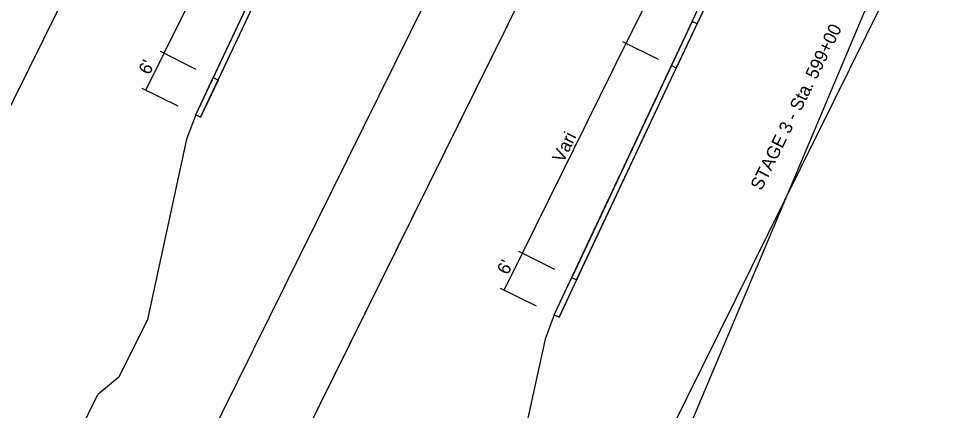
# Model space of a CAD drawing. Extents: x 14104283 to 14120882, y 8635219 to 8671666.
# Drawn here: x 14118051 to 14118626, y 8668145 to 8668387 of the extents above; entities that cross this region are included whole.
import ezdxf

# ---------------------------------------------------------------- set-up
doc = ezdxf.new("R2010")
doc.units = 0
for name, color, linetype in [('Default', 7, 'Continuous'), ('dsnNonPlotable', 7, 'Continuous'), ('dsnStgShadingPrevPav', 7, 'Continuous'), ('dsnTextFinalPlan', 7, 'Continuous'), ('dsnTextOverlapEven', 7, 'Continuous'), ('TC_SubstrataExistingPavement', 7, 'Continuous'), ('Terrain', 7, 'Continuous')]:
    doc.layers.add(name, color=color, linetype=linetype)

msp = doc.modelspace()

# ---------------------------------------------------------------- linework, layer by layer
at = {"layer": 'Default'}
for points in [[(14118174.89, 8668349.44), (14118236.5, 8668480.6), (14118249.33, 8668507.9), (14118246.34, 8668509.38), (14118233.51, 8668482.07), (14118171.9, 8668350.92)], [(14118468.01, 8668385.67), (14118483.41, 8668418.45), (14118488.42, 8668429.12), (14118491.41, 8668427.64), (14118471, 8668384.19)], [(14118396.56, 8668225.72), (14118458.17, 8668356.88), (14118471, 8668384.19), (14118468.01, 8668385.67), (14118455.18, 8668358.36), (14118393.57, 8668227.2)]]:
    msp.add_lwpolyline(points, close=True, dxfattribs=at)
at = {"layer": 'dsnNonPlotable'}
for points in [[(14118092.03, 8667853.71), (14118786.76, 8669258.84), (14119692.14, 8668811.2), (14118997.41, 8667406.07)], [(14118056.48, 8667161.91), (14118665.06, 8668606.45), (14119130.44, 8668410.38), (14118521.87, 8666965.84)]]:
    msp.add_lwpolyline(points, close=True, dxfattribs=at)
at = {"layer": 'dsnStgShadingPrevPav'}
for points in [[(14118161.08, 8668327.89), (14118171.9, 8668350.92), (14118174.89, 8668349.44), (14118164.07, 8668326.41)], [(14118382.75, 8668204.17), (14118393.57, 8668227.2), (14118396.56, 8668225.72), (14118385.74, 8668202.69)]]:
    msp.add_lwpolyline(points, close=True, dxfattribs=at)
at = {"layer": 'dsnTextFinalPlan'}
for p, q in [((14118141.41, 8668365.99), (14118205.63, 8668495.86)), ((14118427.29, 8668372.15), (14118448.57, 8668415.17)), ((14118363.08, 8668242.27), (14118427.29, 8668372.15)), ((14118424.84, 8668373.36), (14118447.07, 8668362.37)), ((14118130.14, 8668343.18), (14118141.41, 8668365.99)), ((14118138.96, 8668367.2), (14118161.19, 8668356.21)), ((14118127.69, 8668344.4), (14118149.92, 8668333.4)), ((14118360.63, 8668243.49), (14118382.86, 8668232.49)), ((14118351.81, 8668219.47), (14118363.08, 8668242.27)), ((14118349.36, 8668220.68), (14118371.59, 8668209.69))]:
    msp.add_line(p, q, dxfattribs=at)
for points in [[(14117870.36, 8667977.42), (14118384.92, 8669018.16), (14118565.56, 8668928.85), (14118050.99, 8667888.12)], [(14118092.03, 8667853.71), (14118606.59, 8668894.44), (14118787.23, 8668805.14), (14118272.66, 8667764.4)]]:
    msp.add_lwpolyline(points, close=True, dxfattribs=at)
at = {"layer": 'dsnTextOverlapEven'}
msp.add_lwpolyline([(14117870.36, 8667977.42), (14118384.92, 8669018.16), (14118565.56, 8668928.85), (14118050.99, 8667888.12)], close=True, dxfattribs=at)
at = {"layer": 'TC_SubstrataExistingPavement'}
for p, q in [((14118164.07, 8668326.41), (14118236.5, 8668480.6)), ((14118385.74, 8668202.69), (14118458.17, 8668356.88)), ((14118171.9, 8668350.92), (14118174.89, 8668349.44)), ((14118161.08, 8668327.89), (14118164.07, 8668326.41)), ((14118393.57, 8668227.2), (14118396.56, 8668225.72)), ((14118382.75, 8668204.17), (14118385.74, 8668202.69))]:
    msp.add_line(p, q, dxfattribs=at)
msp.add_lwpolyline([(14118511.64, 8668478.53), (14118514.63, 8668477.06), (14118458.17, 8668356.88), (14118455.18, 8668358.36)], dxfattribs=at)
at = {"layer": 'Terrain'}
for p, q in [((14118161.08, 8668327.89), (14118233.51, 8668482.07)), ((14118455.18, 8668358.36), (14118511.64, 8668478.53)), ((14118382.75, 8668204.17), (14118455.18, 8668358.36)), ((14118161.08, 8668327.89), (14118155.41, 8668312.82)), ((14118155.41, 8668312.82), (14118131.11, 8668201.36)), ((14118382.75, 8668204.17), (14118377.08, 8668189.1)), ((14118131.11, 8668201.36), (14118113.38, 8668165.5)), ((14118377.08, 8668189.1), (14118352.78, 8668077.64)), ((14118113.38, 8668165.5), (14118100.54, 8668154.92)), ((14118032.46, 8668017.23), (14118100.54, 8668154.92))]:
    msp.add_line(p, q, dxfattribs=at)

# ---------------------------------------------------------------- texts
at = {"layer": 'dsnTextFinalPlan'}
for s, p in [('STAGE 3 - Sta. 599+00', (14118510.81, 8668280.55)), ("6'", (14118132.36, 8668352.15)), ('Vari', (14118388.28, 8668297.71)), ("6'", (14118354.03, 8668228.43))]:
    msp.add_text(s, height=8, rotation=63.69111, dxfattribs=at).set_placement(p)

doc.saveas('drawing.dxf')
